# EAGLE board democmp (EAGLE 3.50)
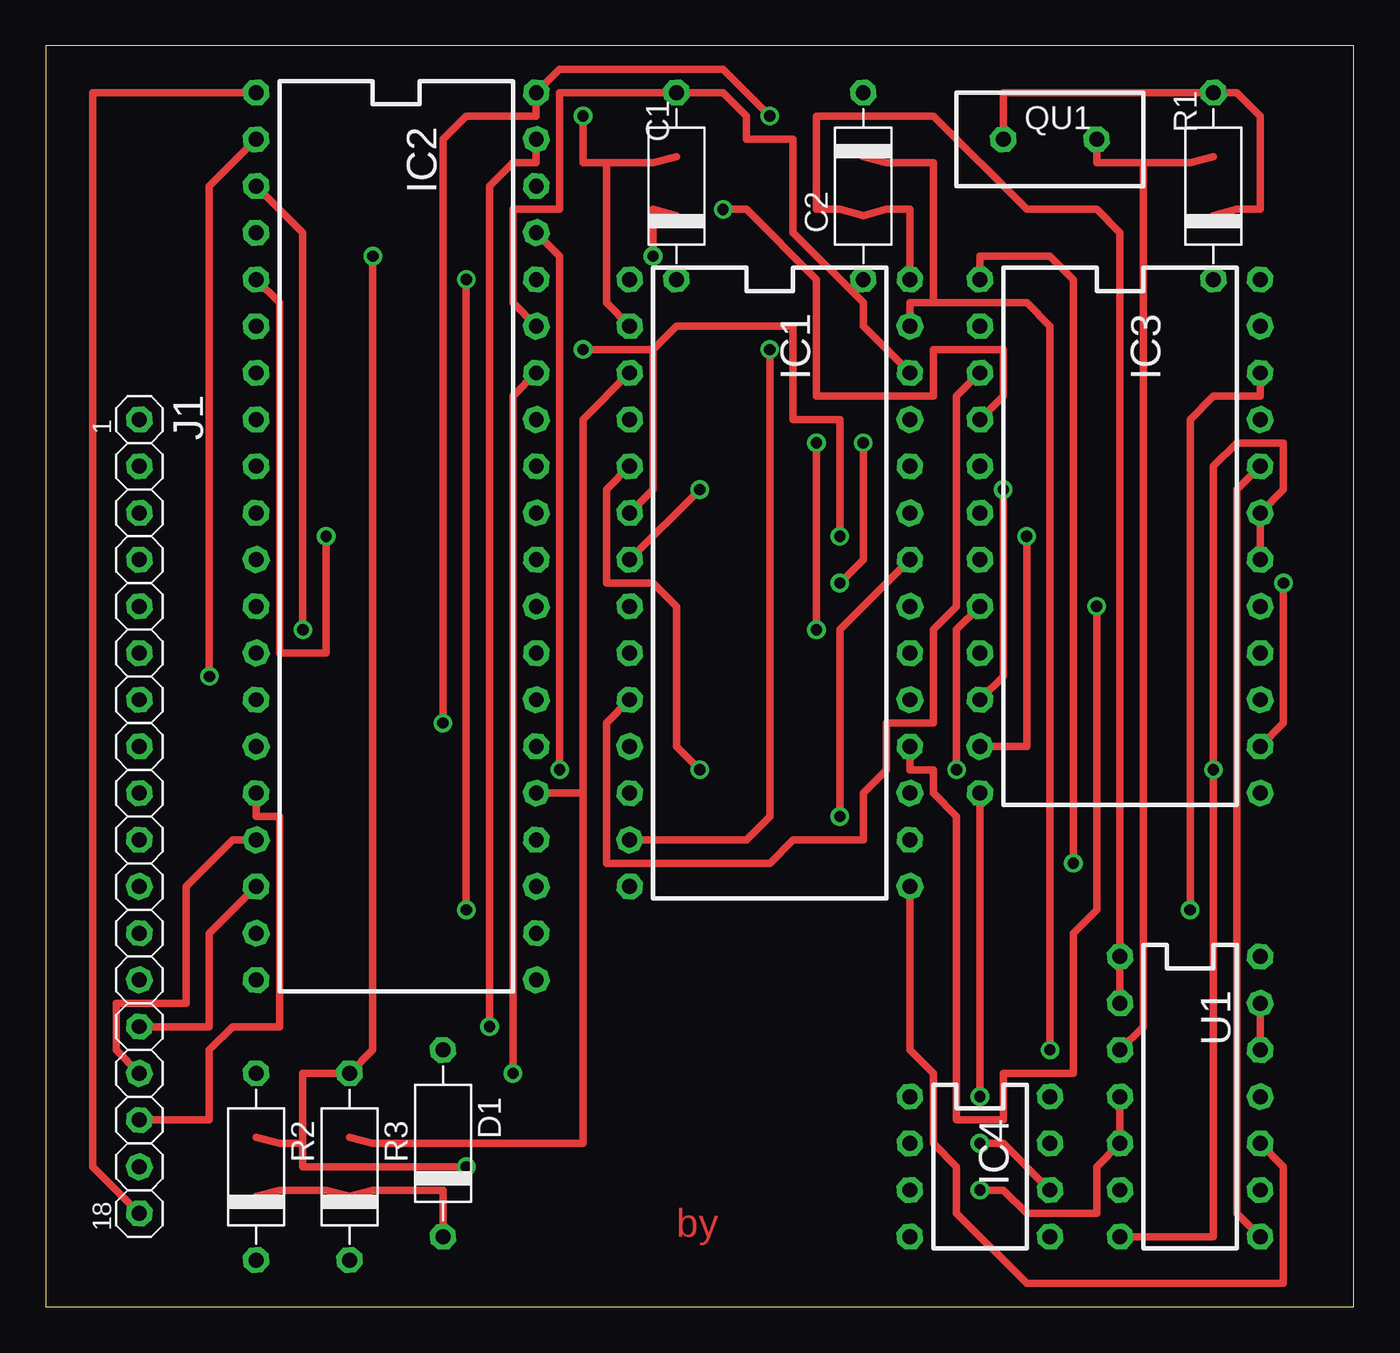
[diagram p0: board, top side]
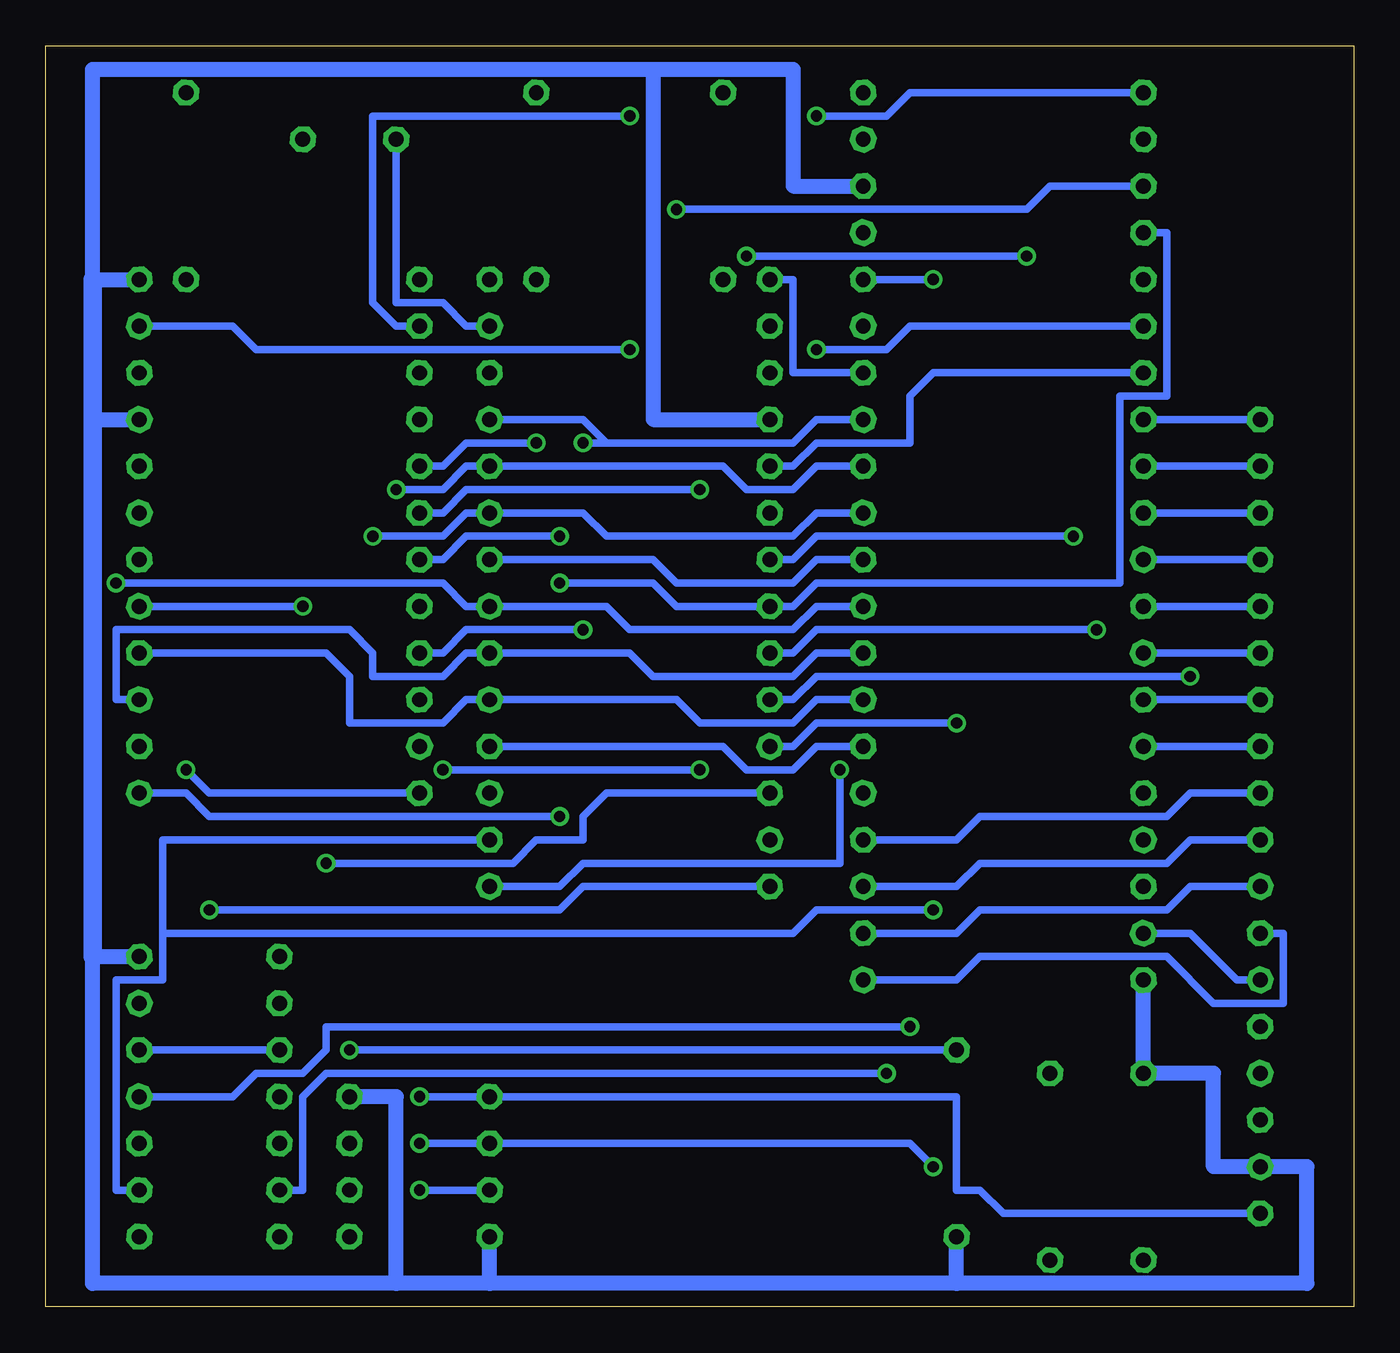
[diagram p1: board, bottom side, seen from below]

Size 71.12 x 68.58 mm. Coordinates in mm from the lower left corner, seen from the top.
Outline: 0,0 71.12,0 71.12,68.58 0,68.58 0,0
Copper layers used: Top, Bottom
tRestrict: area 26.7,0 to 44.5,8.9

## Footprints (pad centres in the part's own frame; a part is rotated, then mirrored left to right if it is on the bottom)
10 = drill 0.813 pad 1.397 octagon:  -5.08,0;  5.08,0
L28 = drill 0.813 pad 1.397 octagon:  -15.24,-7.62;  -12.7,-7.62;  -10.16,-7.62;  -7.62,-7.62;  -5.08,-7.62;  -2.54,-7.62;  0,-7.62;  2.54,-7.62;  5.08,-7.62;  7.62,-7.62;  10.16,-7.62;  12.7,-7.62;  15.24,-7.62;  17.78,-7.62;  17.78,7.62;  15.24,7.62;  12.7,7.62;  10.16,7.62;  7.62,7.62;  5.08,7.62;  2.54,7.62;  0,7.62;  -2.54,7.62;  -5.08,7.62;  -7.62,7.62;  -10.16,7.62;  -12.7,7.62;  -15.24,7.62
L40 = drill 0.813 pad 1.397 octagon:  -21.59,-7.62;  -19.05,-7.62;  -16.51,-7.62;  -13.97,-7.62;  -11.43,-7.62;  -8.89,-7.62;  -6.35,-7.62;  -3.81,-7.62;  -1.27,-7.62;  1.27,-7.62;  3.81,-7.62;  6.35,-7.62;  8.89,-7.62;  11.43,-7.62;  13.97,-7.62;  16.51,-7.62;  19.05,-7.62;  21.59,-7.62;  24.13,-7.62;  26.67,-7.62;  26.67,7.62;  24.13,7.62;  21.59,7.62;  19.05,7.62;  16.51,7.62;  13.97,7.62;  11.43,7.62;  8.89,7.62;  6.35,7.62;  3.81,7.62;  1.27,7.62;  -1.27,7.62;  -3.81,7.62;  -6.35,7.62;  -8.89,7.62;  -11.43,7.62;  -13.97,7.62;  -16.51,7.62;  -19.05,7.62;  -21.59,7.62
L24 = drill 0.813 pad 1.397 octagon:  -13.97,-7.62;  -11.43,-7.62;  -8.89,-7.62;  -6.35,-7.62;  -3.81,-7.62;  -1.27,-7.62;  1.27,-7.62;  3.81,-7.62;  6.35,-7.62;  8.89,-7.62;  11.43,-7.62;  13.97,-7.62;  13.97,7.62;  11.43,7.62;  8.89,7.62;  6.35,7.62;  3.81,7.62;  1.27,7.62;  -1.27,7.62;  -3.81,7.62;  -6.35,7.62;  -8.89,7.62;  -11.43,7.62;  -13.97,7.62
L8 = drill 0.813 pad 1.397 octagon:  -3.81,-3.81;  -1.27,-3.81;  1.27,-3.81;  3.81,-3.81;  3.81,3.81;  1.27,3.81;  -1.27,3.81;  -3.81,3.81
18 = drill 0.813 pad 1.397 octagon:  -21.59,0;  -19.05,0;  -16.51,0;  -13.97,0;  -11.43,0;  -8.89,0;  -6.35,0;  -3.81,0;  -1.27,0;  1.27,0;  3.81,0;  6.35,0;  8.89,0;  11.43,0;  13.97,0;  16.51,0;  19.05,0;  21.59,0
 = drill 0.813 pad 1.397 octagon:  -2.54,0;  2.54,0
L14 = drill 0.813 pad 1.397 octagon:  -7.62,-3.81;  -5.08,-3.81;  -2.54,-3.81;  0,-3.81;  2.54,-3.81;  5.08,-3.81;  7.62,-3.81;  7.62,3.81;  5.08,3.81;  2.54,3.81;  0,3.81;  -2.54,3.81;  -5.08,3.81;  -7.62,3.81

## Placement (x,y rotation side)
C1  0.1u  [10]  34.29,60.96 270 top
C2  33p  [10]  44.45,60.96 90 top
D1  1N4148  [10]  21.59,8.89 270 top
IC1  6504  [L28]  39.37,40.64 270 top
IC2  6532  [L40]  19.05,44.45 270 top
IC3  2716  [L24]  58.42,41.91 270 top
IC4  555  [L8]  50.8,7.62 270 top
J1  1X18  [18]  5.08,26.67 270 top
QU1  1MHz  []  54.61,63.5 180 top
R1  330k  [10]  63.5,60.96 270 top
R2  2.2M  [10]  11.43,7.62 270 top
R3  3.3k  [10]  16.51,7.62 270 top
U1  7400  [L14]  62.23,11.43 270 top

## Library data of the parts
C1 C2 D1 IC1-IC4 J1 QU1 R1-R3 U1 = DEMO

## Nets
A0: IC1. IC2. IC3.
A1: IC1. IC2. IC3.
A2: IC1. IC2. IC3.
A3: IC1. IC2. IC3.
A4: IC1. IC2. IC3.
A5: IC1. IC2. IC3.
A6: IC1. IC2. IC3.
A7: IC1. IC3.
A8: IC1. IC3.
A9: IC1. IC3.
D0: IC1. IC2. IC3.
D1: IC1. IC2. IC3.
D2: IC1. IC2. IC3.
D3: IC1. IC2. IC3.
D4: IC1. IC2. IC3.
D5: IC1. IC2. IC3.
D6: IC1. IC2. IC3.
D7: IC1. IC2. IC3.
GND: C1. IC1. IC2. IC3. IC4. J1. U1.
N$1: C2. D1. IC1. QU1. R1.
N$4: C2. IC1. U1.
N$7: IC1. IC2. U1.
N$11: C1. IC4. R2.
N$13: IC4. U1.
N$15: IC3. U1.
N$19: IC1. IC2. U1.
N$20: IC1. IC2. U1.
N$23: IC1. IC2.
N$24: IC2. U1.
N$27: QU1. R1. U1.
N$28: IC1. IC2. R3.
N$29: IC2. J1.
N$30: IC2. J1.
N$31: IC2. J1.
N$32: IC2. J1.
N$33: IC2. J1.
N$34: IC2. J1.
N$35: IC2. J1.
N$36: IC2. J1.
N$37: IC2. J1.
N$38: IC2. J1.
N$39: IC2. J1.
N$40: IC2. J1.
N$41: IC2. J1.
N$42: IC2. J1.
N$43: IC2. J1.
N$44: IC2. J1.
VCC: D1. IC1. IC2. IC3. IC4. J1. R2. R3. U1.

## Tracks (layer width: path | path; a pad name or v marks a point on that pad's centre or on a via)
A0  (via drill 0.61 pad 1.02)
  Top 0.406: 50.8,38.1 49.53,36.83 v49.53,29.21 | v35.56,29.21 34.29,30.48 34.29,38.1 33.02,39.37 30.48,39.37 30.48,44.45 31.75,45.72
  Bottom 0.406: 11.43,50.8 22.86,50.8 24.13,49.53 24.13,46.99 29.21,46.99 30.48,45.72 31.75,45.72 | v35.56,29.21 v49.53,29.21
A1  (via drill 0.61 pad 1.02)
  Top 0.406: v29.21,52.07 33.02,52.07 | 33.02,52.07 33.02,44.45 31.75,43.18 | v43.18,41.91 43.18,48.26 40.64,48.26 40.64,53.34 34.29,53.34 33.02,52.07
  Bottom 0.406: 11.43,53.34 24.13,53.34 25.4,52.07 v29.21,52.07 | 50.8,40.64 49.53,40.64 48.26,41.91 v43.18,41.91
A2  (via drill 0.61 pad 1.02)
  Top 0.406: 11.43,55.88 12.7,54.61 12.7,35.56 15.24,35.56 v15.24,41.91 | 31.75,40.64 v35.56,44.45
  Bottom 0.406: v15.24,41.91 29.21,41.91 30.48,40.64 31.75,40.64 | 50.8,43.18 49.53,43.18 48.26,44.45 v35.56,44.45
A3  (via drill 0.61 pad 1.02)
  Top 0.406: v43.18,39.37 44.45,40.64 v44.45,46.99
  Bottom 0.406: 11.43,58.42 10.16,58.42 10.16,49.53 12.7,49.53 12.7,39.37 29.21,39.37 30.48,38.1 31.75,38.1 36.83,38.1 38.1,39.37 v43.18,39.37 | 50.8,45.72 49.53,45.72 48.26,46.99 v44.45,46.99
A4  (via drill 0.61 pad 1.02)
  Top 0.406: v13.97,36.83 13.97,58.42 11.43,60.96 | 50.8,48.26 52.07,49.53 52.07,52.07 48.26,52.07 48.26,49.53 41.91,49.53 41.91,55.88 38.1,59.69 v36.83,59.69
  Bottom 0.406: 31.75,35.56 30.48,35.56 29.21,36.83 v13.97,36.83 | v36.83,59.69 17.78,59.69 16.51,60.96 11.43,60.96
A5  (via drill 0.61 pad 1.02)
  Top 0.406: v8.89,34.29 8.89,60.96 11.43,63.5 | 50.8,50.8 49.53,49.53 49.53,38.1 48.26,36.83 48.26,31.75 45.72,31.75 45.72,29.21 44.45,27.94 44.45,25.4 40.64,25.4 39.37,24.13 30.48,24.13 30.48,31.75 31.75,33.02
  Bottom 0.406: 31.75,33.02 30.48,33.02 29.21,34.29 v8.89,34.29
A6  (via drill 0.61 pad 1.02)
  Top 0.406: v21.59,31.75 21.59,63.5 22.86,64.77 26.67,64.77 IC2. 27.94,67.31 36.83,67.31 v39.37,64.77
  Bottom 0.406: 31.75,30.48 30.48,30.48 29.21,31.75 v21.59,31.75 | 50.8,53.34 52.07,53.34 53.34,54.61 53.34,64.77 v39.37,64.77
A7  (via drill 0.61 pad 1.02)
  Top 0.406: v55.88,24.13 55.88,55.88 54.61,57.15 50.8,57.15 50.8,55.88
  Bottom 0.406: 31.75,27.94 40.64,27.94 41.91,26.67 41.91,25.4 44.45,25.4 45.72,24.13 v55.88,24.13
A8  (via drill 0.61 pad 1.02)
  Top 0.406: 31.75,25.4 38.1,25.4 39.37,26.67 v39.37,52.07
  Bottom 0.406: v39.37,52.07 59.69,52.07 60.96,53.34 66.04,53.34
A9  (via drill 0.61 pad 1.02)
  Top 0.406: v62.23,21.59 62.23,48.26 63.5,49.53 66.04,49.53 66.04,50.8
  Bottom 0.406: 31.75,22.86 41.91,22.86 43.18,21.59 v62.23,21.59
D0  (via drill 0.61 pad 1.02)
  Top 0.406: v41.91,46.99 v41.91,36.83
  Bottom 0.406: 26.67,48.26 29.21,48.26 30.48,46.99 40.64,46.99 | 40.64,46.99 41.91,48.26 46.99,48.26 | 50.8,35.56 49.53,35.56 48.26,36.83 v41.91,36.83 | 40.64,46.99 v41.91,46.99
D1  (via drill 0.61 pad 1.02)
  Top 0.406: 50.8,33.02 52.07,34.29 v52.07,44.45
  Bottom 0.406: 26.67,45.72 29.21,45.72 30.48,44.45 33.02,44.45 34.29,45.72 46.99,45.72 48.26,45.72 49.53,44.45 v52.07,44.45
D2  (via drill 0.61 pad 1.02)
  Top 0.406: 50.8,30.48 53.34,30.48 v53.34,41.91
  Bottom 0.406: 26.67,43.18 29.21,43.18 30.48,41.91 40.64,41.91 41.91,43.18 46.99,43.18 48.26,43.18 49.53,41.91 v53.34,41.91
D3  (via drill 0.61 pad 1.02)
  Top 0.406: v43.18,26.67 43.18,36.83 46.99,40.64
  Bottom 0.406: 26.67,40.64 29.21,40.64 30.48,39.37 36.83,39.37 38.1,40.64 46.99,40.64 | 66.04,27.94 63.5,27.94 62.23,26.67 v43.18,26.67
D4  (via drill 0.61 pad 1.02)
  Top 0.406: 66.04,30.48 67.31,31.75 v67.31,39.37
  Bottom 0.406: 26.67,38.1 29.21,38.1 30.48,36.83 39.37,36.83 40.64,38.1 46.99,38.1 48.26,38.1 49.53,39.37 v67.31,39.37
D5
  Bottom 0.406: 26.67,35.56 29.21,35.56 30.48,34.29 38.1,34.29 39.37,35.56 46.99,35.56 48.26,35.56 49.53,34.29 53.34,34.29 53.34,35.56 54.61,36.83 67.31,36.83 67.31,33.02 66.04,33.02
D6
  Bottom 0.406: 26.67,33.02 29.21,33.02 30.48,31.75 35.56,31.75 36.83,33.02 46.99,33.02 48.26,33.02 49.53,31.75 54.61,31.75 54.61,34.29 55.88,35.56 66.04,35.56
D7  (via drill 0.61 pad 1.02)
  Top 0.406: v57.15,38.1 57.15,21.59 55.88,20.32 55.88,12.7 52.07,12.7 52.07,10.16 49.53,10.16 49.53,26.67 48.26,27.94 48.26,29.21 46.99,29.21 46.99,30.48
  Bottom 0.406: 26.67,30.48 29.21,30.48 30.48,29.21 33.02,29.21 34.29,30.48 46.99,30.48 | v57.15,38.1 66.04,38.1
GND  (via drill 0.61 pad 1.02)
  Top 0.406: 58.42,3.81 63.5,3.81 v63.5,29.21 63.5,45.72 64.77,46.99 67.31,46.99 67.31,44.45 66.04,43.18 66.04,40.64 | v29.21,64.77 29.21,62.23 30.48,62.23 | 30.48,62.23 33.02,62.23 34.29,62.56 | 31.75,53.34 30.48,54.61 30.48,62.23 | v50.8,11.43 50.8,27.94 | 11.43,66.04 2.54,66.04 2.54,7.62 J1.
  Bottom 0.406: 11.43,66.04 24.13,66.04 25.4,64.77 v29.21,64.77 | J1. 19.05,5.08 20.32,6.35 21.59,6.35 21.59,11.43 46.99,11.43 v50.8,11.43 | v63.5,29.21 62.23,27.94 50.8,27.94
N$1  (via drill 0.61 pad 1.02)
  Top 0.406: v54.61,13.97 54.61,53.34 53.34,54.61 48.26,54.61 | 48.26,54.61 46.99,54.61 46.99,53.34 | QU1. 52.07,66.04 64.77,66.04 66.04,64.77 66.04,59.69 64.77,59.69 63.5,59.36 | 48.26,54.61 48.26,62.23 45.72,62.23 44.45,62.56
  Bottom 0.406: 21.59,13.97 v54.61,13.97 | QU1. 52.07,54.61 49.53,54.61 48.26,53.34 46.99,53.34
N$4
  Top 0.406: 58.42,16.51 58.42,19.05 58.42,58.42 57.15,59.69 53.34,59.69 48.26,64.77 41.91,64.77 41.91,59.69 43.18,59.69 44.45,59.36 45.72,59.69 46.99,59.69 IC1.
N$7  (via drill 0.61 pad 1.02)
  Top 0.406: v25.4,12.7 25.4,49.53 26.67,50.8
  Bottom 0.406: 58.42,6.35 57.15,6.35 57.15,11.43 55.88,12.7 v25.4,12.7 | 31.75,55.88 30.48,55.88 30.48,50.8 26.67,50.8
N$11  (via drill 0.61 pad 1.02)
  Top 0.406: 54.61,6.35 52.07,8.89 v50.8,8.89 | 13.97,8.89 12.7,8.89 11.43,9.22 | 13.97,8.89 13.97,7.62 v22.86,7.62 | v33.02,57.15 33.02,59.69 34.29,59.36 | v17.78,57.15 17.78,13.97 16.51,12.7 13.97,12.7 13.97,8.89
  Bottom 0.406: v50.8,8.89 46.99,8.89 24.13,8.89 v22.86,7.62 | v17.78,57.15 v33.02,57.15
N$13  (via drill 0.61 pad 1.02)
  Top 0.406: v50.8,6.35 52.07,6.35 53.34,5.08 57.15,5.08 57.15,7.62 58.42,8.89 58.42,11.43
  Bottom 0.406: 46.99,6.35 v50.8,6.35
N$15
  Top 0.406: 66.04,3.81 64.77,5.08 64.77,44.45 66.04,45.72
N$19  (via drill 0.61 pad 1.02)
  Top 0.406: v22.86,21.59 v22.86,55.88
  Bottom 0.406: 66.04,6.35 67.31,6.35 67.31,17.78 64.77,17.78 64.77,20.32 | 64.77,20.32 64.77,25.4 46.99,25.4 | v22.86,55.88 26.67,55.88 | v22.86,21.59 29.21,21.59 30.48,20.32 64.77,20.32
N$20  (via drill 0.61 pad 1.02)
  Top 0.406: 46.99,22.86 46.99,13.97 48.26,12.7 48.26,8.89 49.53,7.62 49.53,5.08 53.34,1.27 67.31,1.27 67.31,7.62 66.04,8.89 | 26.67,58.42 27.94,57.15 v27.94,29.21
  Bottom 0.406: v27.94,29.21 27.94,24.13 41.91,24.13 43.18,22.86 46.99,22.86
N$23
  Top 0.406: 26.67,53.34 25.4,54.61 25.4,59.69 27.94,59.69 27.94,66.04 36.83,66.04 38.1,64.77 38.1,63.5 40.64,63.5 40.64,58.42 44.45,54.61 44.45,53.34 46.99,50.8
N$24  (via drill 0.61 pad 1.02)
  Top 0.406: v24.13,15.24 24.13,60.96 25.4,62.23 26.67,62.23 26.67,63.5
  Bottom 0.406: 66.04,11.43 60.96,11.43 59.69,12.7 57.15,12.7 55.88,13.97 55.88,15.24 v24.13,15.24
N$27
  Top 0.406: 57.15,63.5 57.15,62.23 59.69,62.23 | 59.69,62.23 62.23,62.23 63.5,62.56 | 66.04,13.97 66.04,16.51 | 59.69,62.23 59.69,15.24 58.42,13.97
  Bottom 0.406: 58.42,13.97 66.04,13.97
N$28
  Top 0.406: 29.21,27.94 26.67,27.94 | 29.21,27.94 29.21,48.26 31.75,50.8 | 29.21,27.94 29.21,8.89 17.78,8.89 16.51,9.22
N$29
  Bottom 0.406: 5.08,48.26 11.43,48.26
N$30
  Bottom 0.406: 5.08,45.72 11.43,45.72
N$31
  Bottom 0.406: 5.08,43.18 11.43,43.18
N$32
  Bottom 0.406: 5.08,40.64 11.43,40.64
N$33
  Bottom 0.406: 5.08,38.1 11.43,38.1
N$34
  Bottom 0.406: 5.08,35.56 11.43,35.56
N$35
  Bottom 0.406: 5.08,33.02 11.43,33.02
N$36
  Bottom 0.406: 5.08,30.48 11.43,30.48
N$37
  Top 0.406: 5.08,10.16 8.89,10.16 8.89,13.97 10.16,15.24 12.7,15.24 12.7,26.67 11.43,26.67 11.43,27.94
N$38
  Top 0.406: 5.08,12.7 3.81,13.97 3.81,16.51 7.62,16.51 7.62,22.86 10.16,25.4 11.43,25.4
N$39
  Top 0.406: 5.08,15.24 8.89,15.24 8.89,20.32 11.43,22.86
N$40
  Bottom 0.406: 5.08,17.78 6.35,17.78 8.89,20.32 11.43,20.32
N$41
  Bottom 0.406: 5.08,20.32 3.81,20.32 3.81,16.51 7.62,16.51 10.16,19.05 20.32,19.05 21.59,17.78 26.67,17.78
N$42
  Bottom 0.406: 5.08,22.86 8.89,22.86 10.16,21.59 20.32,21.59 21.59,20.32 26.67,20.32
N$43
  Bottom 0.406: 5.08,25.4 8.89,25.4 10.16,24.13 20.32,24.13 21.59,22.86 26.67,22.86
N$44
  Bottom 0.406: 5.08,27.94 8.89,27.94 10.16,26.67 20.32,26.67 21.59,25.4 26.67,25.4
VCC
  Top 0.406: 11.43,6.02 12.7,6.35 15.24,6.35 16.51,6.02 17.78,6.35 21.59,6.35 D1.
  Bottom 0.813: 11.43,17.78 11.43,12.7 7.62,12.7 7.62,7.62 5.08,7.62 2.54,7.62 2.54,1.27 21.59,1.27 | 21.59,1.27 D1. | 21.59,1.27 46.99,1.27 | 46.99,1.27 46.99,3.81 | 46.99,1.27 52.07,1.27 | 52.07,1.27 52.07,11.43 IC4. | U1. 68.58,19.05 68.58,1.27 52.07,1.27 | IC3. 68.58,55.88 68.58,67.31 38.1,67.31 | 68.58,48.26 66.04,48.26 | 26.67,60.96 30.48,60.96 30.48,67.31 38.1,67.31 | 31.75,48.26 38.1,48.26 38.1,67.31
  Bottom 1.016: 68.58,55.88 68.58,48.26 68.58,19.05

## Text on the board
Top: by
